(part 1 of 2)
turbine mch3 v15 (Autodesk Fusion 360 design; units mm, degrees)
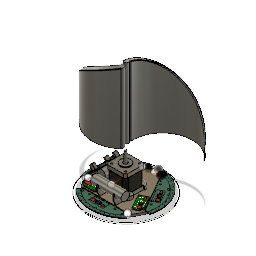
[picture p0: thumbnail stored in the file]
part number: 1uF
part number: ATTINY44-SSU
part number: 5v
part number: isp
part number: power
part number: 499
part number: rgb
parameter "Gapfit" = 0.1
parameter "GapSlide" = 0.3
parameter "RollDiameter" = 7
parameter "Screws" = 3
parameter "Bladediameter" = 250
parameter "Corediameter" = 25
parameter "Bladeball" = 10
sketch "Sketch1" plane through (0, 0, 0) normal (0, 1, 0) x axis (1, 0, 0)
  line L1 (-10, 0) -> (0, 0)
  circle C1 centre (0, 0) radius 125
  circle C2 centre (57.1021, -7.0184) radius 67.4682
  circle C3 centre (-22.4729, 52.9611) radius 67.4682
  circle C4 centre (-34.6292, -45.9427) radius 67.4682
  circle C5 centre (0, 0) radius 12.5
  circle C6 centre (-2.7386, 7.25) radius 5
  arc A1 centre (57.1187, -6.8729) radius 67.4697 clockwise from (-10, 0) to (124.0664, -15.249)
  arc A2 centre (61.6527, -10.7204) radius 62.5778 clockwise from (0, 0) to (124.0664, -15.249)
  arc A3 centre (2.8269, 10.2382) radius 1.879 clockwise from (2.1013, 8.505) to (3.3607, 12.0398)
  arc A4 centre (-21.5422, 58.753) radius 62.5778 clockwise from (0, 0) to (-48.8272, 115.0691)
  arc A5 centre (-22.6072, 52.9027) radius 67.4697 clockwise from (5, -8.6603) to (-48.8272, 115.0691)
  circle C7 centre (-4.9094, -5.9967) radius 5
  arc A6 centre (-10.28, -2.6709) radius 1.879 clockwise from (-8.4162, -2.4327) to (-12.1071, -3.1094)
  arc A7 centre (-40.1105, -48.0326) radius 62.5778 clockwise from (0, 0) to (-75.2392, -99.8202)
  arc A8 centre (-34.5115, -46.0298) radius 67.4697 clockwise from (5, 8.6603) to (-75.2392, -99.8202)
  circle C8 centre (7.648, -1.2533) radius 5
  arc A9 centre (7.4531, -7.5673) radius 1.879 clockwise from (6.3149, -6.0723) to (8.7464, -8.9303)
  point P6 (-10, 0)
  point P8 (0, 0)
  point P7 (0, 0)
  point P9 (-2.7386, 7.25)
  point P3 (57.1021, -7.0184)
  dimension "d1" diameter C1 = 250 (= "Bladediameter")
  dimension "d6" diameter C5 = 25
  dimension "d7" distance P6 P8 = 10
  dimension "d121" distance P7 P9 = 7.75
  dimension "d122" distance L1 P9 = 7.25
  dimension "d123" diameter C6 = 10 (= "Bladeball")
  dimension "d127" distance P3 P7 = 57.1021
  dimension "d133" radius A1 = 67.4697
  dimension "d134" radius A2 = 62.5778
  dimension "d135" radius A3 = 1.879
  dimension "d3" C-Pattern1-Angle = 360
  dimension "d137" C-Pattern2-Angle = 360
extrude "Extrude1" new body sketch "Sketch1" profile of C5 L1 C6 A1 A2 A3 A4 C7 A6 A7 C8 A9 along normal blind 150
extrude "Extrude2" new body sketch "Sketch1" profile of C5 C6 A1 A2 A3 A4 A5 C7 A6 A7 A8 C8 A9 along normal blind 150
extrude "Extrude1" new body sketch "Sketch1" profile of C5 L1 C6 along normal blind 120
combine "Combine1"
sketch "Sketch2"
  line L1 (0, 130) -> (0, 0)
  line L2 (-125, 0) -> (125, 0)
  line L3 (125, 150) -> (0, 150)
  line L4 (125, 0) -> (125, 150)
  line L5 (140, 150) -> (125, 150)
  line L6 (140, 0) -> (140, 150)
  line L7 (125, 0) -> (140, 0)
  line L8 (125, 150) -> (125, 0)
  arc A1 centre (-26.9994, 0.4171) radius 152 clockwise from (0, 150) to (125, 0)
  point P6 (0, 150)
  point P9 (0, 0)
  point P10 (125, 150)
  point P12 (140, 150)
  dimension "d18" angle L1 L2 = 90
  dimension "d114" distance P6 P9 = 150
  dimension "d115" radius A1 = 152
  dimension "d152" distance P10 P12 = 15
revolve "Revolve1" sketch "Sketch2" AlongAngle 360
sketch "Sketch3"
  line L1 (-160.3082, 0) -> (0, 0)
  line L2 (-12.5, 0) -> (12.5, 0)
  line L3 (-125, 0) -> (125, 0)
  line L4 (-9, -2) -> (0, -2)
  line L5 (0, 0) -> (0, -2)
  arc A1 centre (-9, -23.462) radius 21.462 clockwise from (-18.5775, -4.2555) to (-9, -2)
  arc A2 centre (54.8964, -102.7197) radius 122.8561 clockwise from (-18.5775, -4.2555) to (-12.5, 0)
  dimension "d23" distance L3 L4 = 2
revolve "Revolve2" sketch "Sketch3" AlongAngle 360
sketch "Sketch4" plane through (0, -2, 0) normal (0, -1, 0) x axis (1, 0, 0)
  circle C1 centre (0, 0) radius 9
sketch "Sketch1" plane through (0, 0, 0) normal (0, 1, 0) x axis (1, 0, 0)
  line L1 (-20.95, -20.95) -> (20.95, -20.95)
  line L2 (-20.95, 20.95) -> (-20.95, -20.95)
  line L3 (20.95, 20.95) -> (-20.95, 20.95)
  line L4 (20.95, -20.95) -> (20.95, 20.95)
  line L5 (-20.95, 20.95) -> (20.95, -20.95)
  line L6 (20.95, 20.95) -> (-20.95, -20.95)
  line L7 (20.95, 16.85) -> (16.85, 20.95)
  line L8 (-16.85, -20.95) -> (-20.95, -16.85)
  line L9 (0, -20.95) -> (0, 20.95)
  line L10 (16.85, -20.95) -> (20.95, -16.85)
  line L11 (-20.95, 16.85) -> (-16.85, 20.95)
  line L12 (-1.9, -1.6248) -> (-1.9, 1.6248)
  circle C1 centre (14.8, 14.8) radius 2.05
  circle C2 centre (0, 0) radius 11
  circle C3 centre (-14.8, 14.8) radius 2.05
  circle C4 centre (-14.8, -14.8) radius 2.05
  circle C5 centre (14.8, -14.8) radius 2.05
  circle C6 centre (0, 0) radius 4.5
  circle C7 centre (0, 0) radius 2.5
  point P2 (20.95, -20.95)
  point P3 (-20.95, -20.95)
  point P5 (20.95, 20.95)
  point P7 (14.8, 14.8)
  point P13 (20.95, 16.85)
  point P22 (0, 0)
  dimension "d1_1" distance P2 P3 = 41.9
  dimension "d2_1" distance P2 P5 = 41.9
  dimension "d3_1" diameter C1 = 4.1
  dimension "d4" distance L4 P7 = 6.15
  dimension "d5" diameter C2 = 22
  dimension "d8_1" distance L3 P13 = 4.1
  dimension "d9_1" diameter C6 = 9
  dimension "d10" diameter C7 = 5
  dimension "d11" distance P22 L12 = 1.9
  dimension "d7_1" C-Pattern1-Angle = 360
extrude "Extrude1" new body sketch "Sketch1" profile of L1 L2 L3 L4 C1 C2 C3 C4 C5 L7 L8 L10 L11 along normal blind 8 named "d12_1"
extrude "Extrude2" add sketch "Sketch1" profile of C2 C6 along normal blind 10 named "d14_1"
extrude "Extrude3" new body sketch "Sketch1" profile of C7 L12 along normal blind 22.3 named "d16_1"
extrude "Extrude4" add sketch "Sketch1" profile of C7 L12 along normal blind 11 named "d18_1"
extrude "Extrude5" add sketch "Sketch1" profile of C6 C7 along normal blind 7 named "d20_1"
extrude "Extrude6" add of existing geometry blind 10
sketch "Sketch2" plane through (0, 0, 0) normal (0, 1, 0) x axis (1, 0, 0)
  line L1 (-20.95, -20.95) -> (20.95, -20.95)
  line L2 (20.95, -20.95) -> (20.95, 20.95)
  line L3 (20.95, 16.85) -> (20.95, -16.85)
  line L4 (20.95, -16.85) -> (20.95, 16.85)
  line L5 (20.95, -14.0216) -> (14.0216, -20.95)
  line L6 (16.85, -20.95) -> (20.95, -16.85)
  line L7 (20.95, 20.95) -> (-20.95, -20.95)
  line L8 (0, -20.95) -> (0, 20.95)
  line L9 (0, 19) -> (0, -20.95)
  line L10 (-14.0216, 20.95) -> (-20.95, 14.0216)
  line L11 (14.0216, 20.95) -> (20.95, 14.0216)
  line L12 (-20.95, -14.0216) -> (-14.0216, -20.95)
  line L13 (-20.95, -14.0216) -> (-20.95, 14.0216)
  line L14 (14.0216, -20.95) -> (-14.0216, -20.95)
  line L15 (20.95, 14.0216) -> (20.95, -14.0216)
  line L16 (-14.0216, 20.95) -> (14.0216, 20.95)
  dimension "d24_1" angle L1 L5 = 45
  dimension "d25_1" distance L5 L6 = 2
extrude "Extrude7" add sketch "Sketch2" profile of L1 L2 L3 L4 L5 L8 L10 L11 L12 L13 L14 L15 L16 against normal blind 30
work_plane "WorkPlane1" sketch "Sketch1" AlongDistance -15
split "Split1"
sketch "Sketch3" plane through (0, -15, 0) normal (0, 1, 0) x axis (1, 0, 0)
  line L1 (0, 35) -> (0, -30)
copy_paste_bodies "CopyPasteBodies1"
move "Move1" RotateAngle 180
work_plane "WorkPlane2" AlongDistance 0
combine "Combine1"
combine "Combine2"
combine "Combine3"
combine "Combine4"
sketch "Sketch4" plane through (0, -38, 0) normal (0, -1, 0) x axis (1, 0, 0)
  circle C1 centre (0, 0) radius 19.3452
extrude "Extrude8" cut sketch "Sketch4" along normal blind 30
sketch "Sketch5" plane through (0, 0, -20.95) normal (0, 0, -1) x axis (-1, 0, 0)
  line L1 (-16.85, -30) -> (-14.0216, -30)
  line L2 (-16.85, -38) -> (-16.85, -30)
  line L3 (16.85, -38) -> (-16.85, -38)
  line L4 (16.85, -30) -> (16.85, -38)
  line L5 (14.0216, -30) -> (16.85, -30)
  line L6 (14.0216, 0) -> (14.0216, -30)
  line L7 (16.85, 0) -> (14.0216, 0)
  line L8 (16.85, 8) -> (16.85, 0)
  line L9 (-16.85, 8) -> (16.85, 8)
  line L10 (-16.85, 0) -> (-16.85, 8)
  line L11 (-14.0216, 0) -> (-16.85, 0)
  line L12 (-14.0216, -30) -> (-14.0216, 0)
  line L13 (3.75, -30) -> (-3.75, -30)
  line L14 (3.75, -37.5) -> (3.75, -30)
  line L15 (-3.75, -37.5) -> (3.75, -37.5)
  line L16 (-3.75, -30) -> (-3.75, -37.5)
  line L17 (14.0216, -30) -> (-14.0216, -30)
  line L18 (0, -30) -> (0, -37.5)
  point P14 (-3.75, -30)
  point P15 (3.75, -30)
  point P16 (3.75, -37.5)
  dimension "d33" distance P14 P15 = 7.5
  dimension "d34" distance P15 P16 = 7.5
  dimension "d35" distance L3 L15 = 0.5
  dimension "d38" distance L4 L14 = 13.1
  dimension "d39" = 13.2
extrude "Extrude9" cut sketch "Sketch5" profile of L13 L14 L15 L16 against normal blind 1
sketch "Sketch5" plane through (0, -42, 0) normal (0, 1, 0) x axis (-1, 0, 0)
  line L1 (16.85, -20.95) -> (-16.85, -20.95)
  line L2 (20.95, -16.85) -> (16.85, -20.95)
  line L3 (20.95, 16.85) -> (20.95, -16.85)
  line L4 (16.85, 20.95) -> (20.95, 16.85)
  line L5 (-16.85, 20.95) -> (16.85, 20.95)
  line L6 (-20.95, 16.85) -> (-16.85, 20.95)
  line L7 (-20.95, -16.85) -> (-20.95, 16.85)
  line L8 (-16.85, -20.95) -> (-20.95, -16.85)
  line L9 (-14.0216, -20.95) -> (-20.95, -14.0216)
  line L10 (-17.4858, -17.4858) -> (0, 0)
  circle C1 centre (14.8, 14.8) radius 2.05
  circle C2 centre (14.8, -14.8) radius 2.05
  circle C3 centre (-14.8, 14.8) radius 2.05
  circle C4 centre (0, 0) radius 11
  circle C5 centre (-14.8, -14.8) radius 2.05
work_plane "WorkPlane1" RotateAngle 0
sketch "Sketch6" plane through (0, -50, 0) normal (0.7071, 0, 0.7071) x axis (0.7071, 0, -0.7071)
  line L1 (24.7286, 8) -> (0, 8)
  line L2 (24.7286, 18) -> (24.7286, 8)
  line L3 (2.8991, 8) -> (26.7286, 8)
  line L4 (14.8139, 8) -> (24.7286, 8)
  line L5 (14.8139, 10) -> (14.8139, 8)
  line L6 (14.8139, 11) -> (14.8139, 10)
work_plane "WorkPlane2" sketch "Sketch1" AlongDistance 0
split "Split4" bodies "top"
work_plane "WorkPlane3" AlongDistance -30
split "Split5" bodies "middle"
sketch "Top view" plane through (0, 0, 0) normal (0, 1, 0) x axis (1, 0, 0)
  curve K1 (19.1192, 0) -> (9.0783, 0)
  curve K2 (14.0987, 3.55) -> (14.0987, -3.55)
  line L1 (12.7925, 3.4277) -> (0, 0)
  line L2 (12.311, 4.6914) -> (0, 0)
  line L3 (12.311, 4.6914) -> (12.7925, 3.4277)
  circle C1 centre (0, 0) radius 14.0987
  closed curve K3 centre (14.0987, 0)
  circle C2 centre (14.0987, 0) radius 5.0205
  dimension "d10_1" = 7.1 (= "RollDiameter + Gapfit")
  dimension "d11_1" distance K3 = 10.0409 (= "sqrt(2) * d10_1")
  dimension "d12_2" angle K1 L1 = 15 (= "( 180 / NumRolls ) * 1 deg")
sketch "Bearing view"
  line L1 (19.1192, 0) -> (9.0783, 0)
  line L2 (9.0783, 0) -> (19.1192, 0)
  line L3 (14.0987, -5.0205) -> (9.0783, 0)
  line L4 (19.1192, 0) -> (14.0987, -5.0205)
  line L5 (14.0987, 5.0205) -> (9.0783, 0)
  line L6 (19.1192, 0) -> (14.0987, 5.0205)
  line L7 (16.6089, -2.5102) -> (11.5885, 2.5102)
  line L8 (16.6089, 2.5102) -> (11.5885, -2.5102)
  line L9 (14.0987, 5.0205) -> (14.0987, -5.0205)
  line L10 (18.5181, 0.1768) -> (17.3868, 1.3081)
  line L11 (18.2593, -0.7891) -> (18.5181, 0.1768)
  line L12 (14.8879, -4.1606) -> (18.2593, -0.7891)
  line L13 (13.9219, -4.4194) -> (14.8879, -4.1606)
  line L14 (12.7906, -3.288) -> (13.9219, -4.4194)
  line L15 (17.3868, 1.3081) -> (12.7906, -3.288)
  line L16 (24.1757, 0) -> (18.7757, 0)
  line L17 (24.1757, -5.0205) -> (24.1757, 0)
  line L18 (14.8987, -5.0205) -> (24.1757, -5.0205)
  line L19 (14.8987, -4.2912) -> (14.8987, -5.0205)
  line L20 (18.4828, -0.7071) -> (14.8987, -4.2912)
  line L21 (24.1757, 5.0205) -> (24.1757, 0)
  line L22 (14.8987, 5.0205) -> (24.1757, 5.0205)
  line L23 (14.8987, 4.2912) -> (14.8987, 5.0205)
  line L24 (18.4828, 0.7071) -> (14.8987, 4.2912)
  line L25 (4.0218, -5.0205) -> (4.0218, 0)
  line L26 (4.0218, 5.0205) -> (4.0218, 0)
  line L27 (9.7147, 0.7071) -> (13.2987, 4.2912)
  line L28 (9.7147, -0.7071) -> (13.2987, -4.2912)
  line L29 (13.2987, -4.2912) -> (13.2987, -5.0205)
  line L30 (13.2987, -5.0205) -> (4.0218, -5.0205)
  line L31 (13.2987, 5.0205) -> (4.0218, 5.0205)
  line L32 (13.2987, 4.2912) -> (13.2987, 5.0205)
  line L33 (9.4218, 0) -> (4.0218, 0)
  line L34 (19.5757, -5.0205) -> (19.5757, 5.0205)
  line L35 (21.0757, 5.0205) -> (21.0757, -5.0205)
  line L36 (22.5757, -5.0205) -> (22.5757, 5.0205)
  line L37 (7.1218, 5.0205) -> (7.1218, -5.0205)
  line L38 (5.6218, -5.0205) -> (5.6218, 5.0205)
  line L39 (4.0218, 5.0205) -> (0, 5.0205)
  line L40 (4.0218, -5.0205) -> (4.0218, 5.0205)
  line L41 (0, -5.0205) -> (4.0218, -5.0205)
  line L42 (0, 5.0205) -> (0, -5.0205)
  line L43 (0, 0) -> (4.0218, 0)
  arc A1 centre (17.7757, 0) radius 1 clockwise from (18.7757, 0) to (18.4828, -0.7071)
  arc A2 centre (17.7757, 0) radius 1 clockwise from (18.4828, 0.7071) to (18.7757, 0)
  arc A3 centre (10.4218, 0) radius 1 clockwise from (9.4218, 0) to (9.7147, 0.7071)
  arc A4 centre (10.4218, 0) radius 1 clockwise from (9.7147, -0.7071) to (9.4218, 0)
  point P16 (13.9219, -4.4194)
  point P17 (12.7906, -3.288)
  point P6 (14.0987, -5.0205)
  point P31 (18.7757, 0)
  dimension "d32_1" distance L4 L12 = 0.05 (= "Gapfit / 2")
  dimension "d33_1" distance L3 L14 = 0.3 (= "GapSlide")
  dimension "d34_1" angle L13 L14 = 60
  dimension "d35_1" distance L12 P16 = 0.5
  dimension "d36_1" distance P16 P17 = 1.6
  dimension "d45" distance L4 L20 = 0.05 (= "Gapfit / 2")
  dimension "d46" distance P6 L19 = 0.8
  dimension "d47" radius A1 = 1
  dimension "d53" distance P31 L34 = 0.8
  dimension "d54" distance L34 L36 = 3 (= "Screws")
  dimension "d55" distance L21 L36 = 1.6
revolve "Revolve1" sketch "Bearing view" AlongAngle 360 named "d37_1"
circular_pattern "C-Pattern1" countU 6 (= "NumRolls / 2") named "d38_1" TotalAngle 360 named "d39_1"
revolve "Revolve1" sketch "Bearing view" AlongAngle 360 named "d40_1"
move "Move1" RotateAngle 180 named "d41_1"
move "Move2" RotateAngle 30 (= "( 360 / NumRolls ) * 1 deg")
circular_pattern "C-Pattern1" countU 6 (= "NumRolls / 2") TotalAngle 360
revolve "Revolve1" sketch "Bearing view" AlongAngle 360 bodies "Race outer"
revolve "Revolve1" sketch "Bearing view" AlongAngle 360
copy_paste_bodies "CutPasteBodies1"
revolve "Revolve1" sketch "Bearing view" AlongAngle 360 bodies "Race inner top"
revolve "Revolve2" sketch "Bearing view" AlongAngle 360
circular_pattern "C-Pattern1" TotalAngle 360
revolve "Revolve2" sketch "Bearing view" AlongAngle 360
circular_pattern "C-Pattern1" TotalAngle 360
fillet "Fillet1" radius 0.4
fillet "Fillet2" radius 0.4
position "Position1"
extrude "Extrude1" add of existing geometry blind 2.98
revolve "Revolve3" sketch "Bearing view" AlongAngle 360
revolve "Revolve4" sketch "Bearing view" AlongAngle 360 bodies "Race inner top"
combine "Combine1"
work_plane "WorkPlane4" AlongDistance 8
split "Split1" bodies "Race inner top"
position "Position2"
sketch "Sketch7" plane through (0, -2, 0) normal (0, -1, 0) x axis (1, 0, 0)
  circle C1 centre (0, 0) radius 9
position "Position3"
position "Position4"
extrude "Extrude3" add of existing geometry blind 10
sketch "Sketch8"
  line L1 (9, -27) -> (-9, -27)
  line L2 (1.593, 101.3922) -> (1.593, -15)
  line L3 (11, -27) -> (0, -27)
  line L4 (13, -27) -> (13, -29)
  line L5 (11, -27) -> (13, -27)
  line L6 (-15.2987, -28.9795) -> (15.2987, -28.9795)
  line L7 (9, -28.9795) -> (9, -27)
  line L8 (-18.5775, -19.2555) -> (18.5775, -19.2555)
  line L9 (13, -19.2555) -> (13, -29)
  line L10 (9, -19.2555) -> (13, -19.2555)
  line L11 (11, -23) -> (9, -23)
  line L12 (11, -27) -> (11, -23)
  line L13 (11, -27) -> (9, -27)
  line L14 (9, -19.2555) -> (9, -23)
  line L15 (10.8, -23.2) -> (9, -23.2)
  line L16 (10.8, -27) -> (10.8, -23.2)
  line L17 (10.8, -27) -> (9, -27)
  line L18 (9, -27) -> (9, -23.2)
  line L19 (11, -19.2555) -> (11, -23)
  line L20 (9, -27) -> (9, -23)
  line L21 (15.2987, -19.0267) -> (15.2987, -28.9795)
  line L22 (12.5, -15) -> (18.5775, -19.2555)
  line L23 (20.95, -88) -> (20.95, -92)
  line L24 (-16.85, -88) -> (16.85, -88)
  line L25 (0, -88) -> (0, -92)
  line L26 (76.6506, -92) -> (0, -92)
  line L27 (0, -88) -> (75.5922, -88)
  line L28 (24.1757, -29.3795) -> (24.1757, -38.6205)
  line L29 (23.7757, -28.9795) -> (15.2987, -28.9795)
  line L30 (23.7757, -28.9795) -> (24.1757, -29.3795)
  line L31 (78.096, -100.3794) -> (80.0853, -100.3794)
  line L32 (24.1757, -29.3795) -> (24.1757, -38.6205)
  line L33 (24.1757, -29.3795) -> (23.7757, -28.9795)
  arc A1 centre (-5.4766, -109.9537) radius 86.0959 clockwise from (23.7757, -28.9795) to (80.0853, -100.3794)
  arc A2 centre (6.5799, -108.4006) radius 71.9645 clockwise from (24.1757, -38.6205) to (78.096, -100.3794)
  point P30 (20.95, -88)
  point P31 (20.95, -92)
  dimension "d75" distance L11 L15 = 0.2
  dimension "d76" distance L12 L16 = 0.2
  dimension "d96" distance P30 P31 = 4
revolve "Revolve3" sketch "Sketch8" AlongAngle 360
combine "Combine3"
extrude "Extrude4" add of existing geometry blind 2
revolve "Revolve1" sketch "Sketch8" AlongAngle -30
circular_pattern "C-Pattern1" TotalAngle 360
combine "Combine4"
revolve "Revolve8" sketch "Sketch8" AlongAngle 360
revolve "Revolve2" sketch "Sketch8" AlongAngle 30 bodies "race inner"
revolve "Revolve4" sketch "Sketch8" AlongAngle 60
circular_pattern "C-Pattern3" TotalAngle 360
combine "Combine1"
work_plane "WorkPlane5" AlongDistance 0
work_plane "WorkPlane6" AlongDistance 4
sketch "Sketch11" plane through (0, -88, 0) normal (0, -1, 0) x axis (1, 0, 0)
  line L1 (16.85, -20.95) -> (-16.85, -20.95)
  line L2 (20.95, -16.85) -> (16.85, -20.95)
  line L3 (20.95, 16.85) -> (20.95, -16.85)
  line L4 (16.85, 20.95) -> (20.95, 16.85)
  line L5 (-16.85, 20.95) -> (16.85, 20.95)
  line L6 (-20.95, 16.85) -> (-16.85, 20.95)
  line L7 (-20.95, -16.85) -> (-20.95, 16.85)
  line L8 (-16.85, -20.95) -> (-20.95, -16.85)
  circle C1 centre (0, 0) radius 4.5
  circle C2 centre (14.8, 14.8) radius 2.05
  circle C3 centre (-14.8, 14.8) radius 2.05
  circle C4 centre (14.8, -14.8) radius 2.05
  circle C5 centre (-14.8, -14.8) radius 2.05
  circle C6 centre (-14.8, 14.8) radius 2.05
  circle C7 centre (14.8, 14.8) radius 2.05
  circle C8 centre (14.8, -14.8) radius 2.05
  circle C9 centre (-14.8, -14.8) radius 2.05
sketch "Sketch12" plane through (0, -34, 0) normal (0, -1, 0) x axis (1, 0, 0)
  line L1 (-1.9, 1.6248) -> (-1.9, -1.6248)
  circle C1 centre (0, 0) radius 9.4218
  circle C2 centre (5.0358, 5.0358) radius 1.5
  circle C3 centre (0, 7.1218) radius 1.5
  circle C4 centre (-5.0358, 5.0358) radius 1.5
  circle C5 centre (-7.1218, 0) radius 1.5
  circle C6 centre (-5.0358, -5.0358) radius 1.5
  circle C7 centre (0, -7.1218) radius 1.5
  circle C8 centre (7.1218, 0) radius 1.5
  circle C9 centre (5.0358, -5.0358) radius 1.5
  arc A1 centre (0, 0) radius 2.5 clockwise from (-1.9, 1.6248) to (-1.9, -1.6248)
  circle C10 centre (0, 0) radius 2.5
copy_paste_bodies "CutPasteBodies3"
position "Position7"
combine "Combine2"
combine "Combine3"
combine "Combine1"
revolve "Revolve6" sketch "Sketch2" AlongAngle 180
revolve "Revolve7" sketch "Sketch2" AlongAngle -180
split "Split1"
combine "Combine2"
sketch "Sketch15" plane through (0, -14, 0) normal (0, -1, 0) x axis (1, 0, 0)
  line L1 (-1.9, 1.6248) -> (-1.9, -1.6248)
  arc A1 centre (0, 0) radius 2.5 clockwise from (-1.9, 1.6248) to (-1.9, -1.6248)
  circle C1 centre (0, 0) radius 9
extrude "Extrude2" cut sketch "Sketch12" profile of L1 C10 against normal blind 31
extrude "Extrude3" cut of existing geometry to an object
revolve "Revolve8" sketch "Sketch2" AlongAngle 360
revolve "Revolve6" sketch "Sketch8" AlongAngle 360
revolve "Revolve7" sketch "Sketch8" AlongAngle 360
ground "Ground1"
sketch "Sketch16" plane through (0, 0, 0) normal (0, 1, 0) x axis (1, 0, 0)
as_built_joint "As-built2"
position "Position8"
sketch "Sketch17"
  line L1 (18.5775, -19.2555) -> (43, -37)
  line L2 (138.1715, -105.0631) -> (15.2987, -19.0267)
  line L3 (40.6813, -36.7998) -> (15.2987, -19.0267)
  line L4 (43, -37) -> (40.6813, -36.7998)
  line L5 (12.5, -15) -> (18.5775, -19.2555)
  line L6 (15.5388, -17.1278) -> (15.2987, -19.0267)
  line L7 (15.5388, -17.1278) -> (18.5775, -19.2555)
revolve "Revolve3" sketch "Sketch17" AlongAngle 360
move "Move1"
move "Move2" RotateAngle 25
fillet "Fillet1" radius 1
fillet "Fillet2" radius 1
revolve "Revolve8" sketch "Sketch8" AlongAngle 360
revolve "Revolve9" sketch "Sketch8" AlongAngle 360
component_from_bodies "Body->Comp"
sketch "Sketch18" plane through (0, -88, 0) normal (0, 1, 0) x axis (-1, 0, 0)
  circle C1 centre (0, 0) radius 75.5922
pcb "PCB" BoardHeight 1.57 named "d1_2"
position "Position9"
sketch "Sketch19" plane through (0, -90, 0) normal (0, -1, 0) x axis (1, 0, 0)
  line L1 (-52.744, 40.167) -> (-52.641, 74.634)
  line L2 (52.118, 39.984) -> (-52.744, 40.167)
  line L3 (51.967, 74.579) -> (52.118, 39.984)
  line L4 (-52.641, 74.634) -> (51.967, 74.579)
  circle C1 centre (-11.43, 47.272) radius 0.175
  circle C2 centre (-5.461, 64.925) radius 0.175
  circle C3 centre (-26.924, 63.655) radius 0.175
  circle C4 centre (-34.544, 60.861) radius 0.175
  circle C5 centre (14.478, 63.401) radius 0.175
  circle C6 centre (21.336, 61.369) radius 0.175
  circle C7 centre (-44.584, 53.756) radius 0.175
  circle C8 centre (27.273, 58.035) radius 0.175
  circle C9 centre (-11.303, 49.558) radius 0.175
  circle C10 centre (-17.907, 62.766) radius 0.175
  circle C11 centre (18.796, 59.21) radius 0.175
  circle C12 centre (41.275, 51.59) radius 0.175
  circle C13 centre (48.514, 48.161) radius 0.175
  circle C14 centre (7.239, 68.608) radius 0.175
  circle C15 centre (22.225, 64.925) radius 0.175
  circle C16 centre (36.068, 58.194) radius 0.175
  circle C17 centre (44.704, 44.478) radius 0.175
  circle C18 centre (-2.54, 47.907) radius 0.175
  circle C19 centre (39.243, 55.908) radius 0.175
  circle C20 centre (28.956, 62.385) radius 0.175
  circle C21 centre (15.24, 66.957) radius 0.175
  circle C22 centre (-9.525, 65.179) radius 0.175
  circle C23 centre (42.672, 53.368) radius 0.175
  circle C24 centre (34.163, 54.765) radius 0.175
  circle C25 centre (-5.461, 62.766) radius 0.175
  circle C26 centre (42.672, 48.161) radius 0.175
  circle C27 centre (36.83, 52.987) radius 0.175
  circle C28 centre (-38.1, 58.575) radius 0.175
  circle C29 centre (-25.908, 61.369) radius 0.175
  circle C30 centre (-5.461, 69.243) radius 0.175
  circle C31 centre (1.905, 68.989) radius 0.175
  circle C32 centre (-42.862, 51.272) radius 0.175
  circle C33 centre (4.956, 63.524) radius 0.175
  circle C34 centre (-44.704, 46.383) radius 0.175
  circle C35 centre (-15.494, 47.272) radius 0.175
  circle C36 centre (-36, 58) radius 3.0397
  circle C37 centre (-28.8597, 61.8637) radius 3.0397
  circle C38 centre (-21.3112, 64.8524) radius 3.0397
  circle C39 centre (-13.4613, 66.9238) radius 3.0397
  circle C40 centre (-5.4209, 68.0486) radius 3.0397
  circle C41 centre (2.6961, 68.2109) radius 3.0397
  circle C42 centre (10.7749, 67.4085) radius 3.0397
  circle C43 centre (18.7014, 65.6526) radius 3.0397
  circle C44 centre (26.3634, 62.968) radius 3.0397
  circle C45 centre (33.6524, 59.3929) radius 3.0397
  circle C46 centre (40.4655, 54.9777) radius 3.0397
  circle C47 centre (46.7062, 49.7848) radius 3.0397
  dimension "d170" C-Pattern1-Angle = -75
remove_instance "RemoveInstance1"
pcb "PCB" BoardHeight 1.57 named "d1_3"
position "Position11"
work_plane "WorkPlane8" AlongDistance 0
sketch "Sketch20" plane through (0, -88, 0) normal (0, -1, 0) x axis (1, 0, 0)
  line L1 (46.092, 43.282) -> (54.22, 52.172)
  line L2 (54.22, 52.172) -> (46.092, 43.282)
  line L3 (20, 46) -> (-26, 46)
  line L4 (20, 58) -> (20, 46)
  line L5 (-26, 58) -> (20, 58)
  line L6 (-26, 46) -> (-26, 58)
  line L7 (-46.11, 43.282) -> (-55, 52.172)
  line L8 (-46.4835, 42.382) -> (-49.2565, 45.1551)
  line L9 (-46.11, 43.282) -> (46.092, 43.282)
  line L10 (46.4886, 42.382) -> (-46.4835, 42.382)
  line L11 (49.14, 45.2819) -> (46.4886, 42.382)
  line L12 (-63.7853, 19.9155) -> (-59.9482, 19.0693)
  line L13 (-59.9482, 19.0693) -> (-13.4622, -61.4469)
  line L14 (-13.4622, -61.4469) -> (-14.4772, -65.235)
  line L15 (-26.8372, -45.5167) -> (-37.2295, -51.5167)
  line L16 (-49.8372, -5.6795) -> (-26.8372, -45.5167)
  line L17 (-37.2295, -51.5167) -> (-60.2295, -11.6795)
  line L18 (-60.2295, -11.6795) -> (-49.8372, -5.6795)
  line L19 (14.6453, -65.1974) -> (13.4596, -61.4513)
  line L20 (13.4596, -61.4513) -> (59.9456, 19.0649)
  line L21 (59.9456, 19.0649) -> (63.7337, 20.0799)
  line L22 (52.8372, -0.4833) -> (63.2295, -6.4833)
  line L23 (29.8372, -40.3205) -> (52.8372, -0.4833)
  line L24 (63.2295, -6.4833) -> (40.2295, -46.3205)
  line L25 (40.2295, -46.3205) -> (29.8372, -40.3205)
  circle C1 centre (0, 0) radius 74.8422
  arc A1 centre (-1.9164, 1.5567) radius 77.2302 clockwise from (72.6823, 21.5454) to (18.0723, -73.0419)
  circle C2 centre (0, 0) radius 66.8221
  arc A2 centre (2.8846, 66.1916) radius 1.7023 clockwise from (4.5184, 66.6691) to (1.2984, 66.8095)
  arc A3 centre (-58.7659, -30.5977) radius 1.7023 clockwise from (-59.9964, -29.4215) to (-58.5079, -32.2803)
  arc A4 centre (55.8813, -35.5939) radius 1.7023 clockwise from (55.4779, -37.2477) to (57.2095, -34.5292)
  dimension "d231" distance L7 L8 = 0.9005
  dimension "d232" distance L9 L10 = 0.9
  dimension "d233" distance L2 L11 = 0.9
sketch "Sketch21" plane through (0, -89, 0) normal (0, 1, 0) x axis (-1, 0, 0)
  line L1 (-60.5383, 18.2914) -> (-63.9987, 19.2186)
  line L2 (-14.4373, -61.5578) -> (-60.5383, 18.2914)
  line L3 (-15.5248, -64.9936) -> (-14.4373, -61.5578)
  line L4 (14.4283, -61.5734) -> (15.3555, -65.0338)
  line L5 (60.5293, 18.2758) -> (14.4283, -61.5734)
  line L6 (64.0485, 19.0519) -> (60.5293, 18.2758)
  line L7 (46.11, 43.282) -> (48.6432, 45.8152)
  line L8 (-46.092, 43.282) -> (46.11, 43.282)
  line L9 (-48.5237, 45.9417) -> (-46.092, 43.282)
  line L10 (-16.85, 20.95) -> (16.85, 20.95)
  line L11 (16.85, 20.95) -> (-16.85, 20.95)
  line L12 (16.85, 20.95) -> (-16.85, 20.95)
  line L13 (-14.0216, 20.95) -> (14.0216, 20.95)
  line L14 (-4.7919, 20.95) -> (4.7919, 20.95)
  line L15 (0, -35) -> (0, 30)
  line L16 (-4.7919, 30) -> (4.7919, 30)
  line L17 (-4.7919, 20.95) -> (-4.7919, 30)
  line L18 (4.7919, 20.95) -> (4.7919, 30)
  line L19 (-4.7919, 20.95) -> (4.7919, 20.95)
  arc A1 centre (0, 0) radius 66.8221 clockwise from (15.3555, -65.0338) to (-15.5248, -64.9936)
  arc A2 centre (0, 0) radius 66.8221 clockwise from (48.6432, 45.8152) to (64.0485, 19.0519)
  arc A3 centre (0, 0) radius 66.8221 clockwise from (-63.9987, 19.2186) to (-48.5237, 45.9417)
sketch "Sketch22" plane through (17.4858, 0, 17.4858) normal (0.7071, 0, 0.7071) x axis (0.7071, 0, -0.7071)
  line L1 (-4.8991, -80) -> (-4.8991, -50)
  line L2 (4.8991, -80) -> (-4.8991, -80)
  line L3 (4.8991, -50) -> (4.8991, -80)
  line L4 (-4.8991, -50) -> (4.8991, -50)
  line L5 (-2.8991, -80) -> (-26.7286, -80)
  line L6 (4.8991, -80) -> (-6.9957, -80)
  line L7 (26.7286, -88) -> (2.8991, -88)
  line L8 (4.8991, -88) -> (4.8991, -80)
  line L9 (33.3366, -89) -> (-55.7237, -89)
  line L10 (4.8991, -89) -> (4.8991, -88)
  line L11 (6.7296, -78.9998) -> (6.7296, -89)
  line L12 (4.8991, -77.8864) -> (6.7296, -78.9998)
  line L13 (-4.8991, -77.8182) -> (4.8991, -77.8864)
  line L14 (-4.8991, -77.8182) -> (-6.9957, -80)
  line L15 (-2.8991, -80) -> (-6.9957, -80)
  line L16 (4.8991, -80) -> (-6.9957, -80)
  line L17 (12.0731, -80.9886) -> (6.7296, -80.9886)
  arc A1 centre (2.303, -85.0395) radius 10.5766 clockwise from (-6.9957, -80) to (12.4568, -88)
extrude "Extrude1" new body sketch "Sketch22" profile of L1 L2 L3 L5 L6 L7 L8 L9 L10 L11 L12 L13 L14 L15 L16 A1 along normal blind 3
revolve "Revolve1" AlongAngle 90
extrude "Extrude1" new body blind 2
extrude "Extrude2" cut of existing geometry blind 10
remove_instance "RemoveInstance2"
remove_instance "RemoveInstance3"
pcb "PCB" BoardHeight 1.57 named "d1_5"
remove_instance "RemoveInstance4"
position "Position13"
step "C-Pattern" TotalAngle 360
extrude "Extrude1" new body sketch "Sketch20" along normal blind 5
extrude "Extrude2" cut sketch "Sketch20" profile of C1 A1 C2 L1 L2 L7 along normal blind 5
extrude "Extrude3" cut sketch "Sketch20" profile of L3 L4 L5 L6 L15 L16 L17 L18 L22 L23 L24 L25 along normal blind 2
extrude "Extrude4" cut sketch "Sketch20" profile of C2 L1 L2 L3 L4 L5 L6 A2 L7 L9 L12 L13 L14 L15 L16 L17 L18 A3 L19 L20 L21 L22 L23 L24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 along normal blind 0.5
sketch "Sketch24" plane through (0, -88, 0) normal (0, -1, 0) x axis (1, 0, 0)
  line L1 (16.85, -20.95) -> (-16.85, -20.95)
  line L2 (20.95, -16.85) -> (16.85, -20.95)
  line L3 (20.95, 16.85) -> (20.95, -16.85)
  line L4 (16.85, 20.95) -> (20.95, 16.85)
  line L5 (-16.85, 20.95) -> (16.85, 20.95)
  line L6 (-20.95, 16.85) -> (-16.85, 20.95)
  line L7 (-20.95, -16.85) -> (-20.95, 16.85)
  line L8 (-16.85, -20.95) -> (-20.95, -16.85)
  line L9 (11, 45) -> (-20, 45)
  line L10 (11, 59) -> (11, 45)
  line L11 (-20, 59) -> (11, 59)
  line L12 (-20, 45) -> (-20, 59)
  line L13 (-41.0955, -46.8205) -> (-56.5955, -19.9737)
  line L14 (-44.4711, -12.9737) -> (-28.9711, -39.8205)
  line L15 (-56.5955, -19.9737) -> (-44.4711, -12.9737)
  line L16 (-28.9711, -39.8205) -> (-41.0955, -46.8205)
  line L17 (61.0955, -12.1795) -> (45.5955, -39.0263)
  line L18 (33.4711, -32.0263) -> (48.9711, -5.1795)
  line L19 (45.5955, -39.0263) -> (33.4711, -32.0263)
  line L20 (48.9711, -5.1795) -> (61.0955, -12.1795)
  line L21 (26.2941, 8.6775) -> (22.2443, 12.7273)
  circle C1 centre (0, 0) radius 4.5
  circle C2 centre (14.8, 14.8) radius 2.05
  circle C3 centre (-14.8, 14.8) radius 2.05
  circle C4 centre (14.8, -14.8) radius 2.05
  circle C5 centre (-14.8, -14.8) radius 2.05
  circle C6 centre (-28.584, 47.314) radius 1.778
  circle C7 centre (-28.584, 47.314) radius 1.778
  circle C8 centre (-28.584, 47.314) radius 1
  circle C9 centre (25.518, 47.314) radius 1.778
  circle C10 centre (25.518, 47.314) radius 1.778
  circle C11 centre (25.518, 47.314) radius 1
  circle C12 centre (-26.6831, -48.4115) radius 1.778
  circle C13 centre (-53.7341, -1.5578) radius 1
  circle C14 centre (-26.6831, -48.4115) radius 1
  circle C15 centre (-53.7341, -1.5578) radius 1.778
  circle C16 centre (-26.6831, -48.4115) radius 1.778
  circle C17 centre (-53.7341, -1.5578) radius 1.778
  circle C18 centre (55.2671, 1.0975) radius 1.778
  circle C19 centre (28.2161, -45.7562) radius 1
  circle C20 centre (55.2671, 1.0975) radius 1
  circle C21 centre (28.2161, -45.7562) radius 1.778
  circle C22 centre (55.2671, 1.0975) radius 1.778
  circle C23 centre (28.2161, -45.7562) radius 1.778
  arc A1 centre (16.4647, 12.6032) radius 10.5843 clockwise from (12.5391, 22.4325) to (26.2941, 8.6775)
  arc A2 centre (13.8805, 14.0687) radius 8.4707 clockwise from (12.5391, 22.4325) to (22.2443, 12.7273)
  dimension "d244" diameter C8 = 2
  dimension "d245" diameter C11 = 2
  dimension "d257" C-Pattern1-Angle = 360
extrude "Extrude5" cut of existing geometry blind -2
extrude "Extrude6" cut of existing geometry blind -1
extrude "Extrude7" add of existing geometry blind 0.5
extrude "Extrude8" cut sketch "Sketch24" profile of L9 L10 L11 L12 along normal blind 2
extrude "Extrude9" cut sketch "Sketch20" profile of C2 L1 L2 L7 L8 L9 L10 L11 along normal blind 2
extrude "Extrude10" cut sketch "Sketch24" profile of L17 L18 L19 L20 along normal blind 2
extrude "Extrude11" cut sketch "Sketch24" profile of L13 L14 L15 L16 along normal blind 2
extrude "Extrude12" cut of existing geometry blind -2
extrude "Extrude13" add of existing geometry blind 1.5
extrude "Extrude14" cut sketch "Sketch24" profile of L17 L18 L19 L20 along normal blind 2
extrude "Extrude15" cut of existing geometry blind -1
extrude "Extrude16" add of existing geometry blind 1.5
extrude "Extrude17" cut sketch "Sketch24" profile of L13 L14 L15 L16 along normal blind 2
extrude "Extrude18" cut of existing geometry blind -2
extrude "Extrude19" new body sketch "Sketch24" profile of C14 against normal blind 5
extrude "Extrude20" new body sketch "Sketch24" profile of C13 against normal blind 5
extrude "Extrude21" new body sketch "Sketch24" profile of C8 against normal blind 5
extrude "Extrude22" new body sketch "Sketch24" profile of C11 against normal blind 5
extrude "Extrude23" new body sketch "Sketch24" profile of C19 against normal blind 5
extrude "Extrude24" new body sketch "Sketch24" profile of C20 against normal blind 5
pcb "PCB1" BoardHeight 1.57 named "d1_6"
revolve "Revolve1" sketch "Sketch22" AlongAngle 90
extrude "Extrude1" add of existing geometry to an object
combine "Combine1"
position "Position15"
sketch "Sketch25" plane through (0, -88, 0) normal (0, -1, 0) x axis (1, 0, 0)
  line L1 (-54.1235, 39.1897) -> (-50.7211, 39.2347)
  line L2 (-57.0548, 34.7842) -> (-57.0711, 32.8847)
  line L3 (-50.7211, 39.2347) -> (-57.0711, 32.8847)
  circle C1 centre (-29.1311, 34.1547) radius 1.796
  circle C2 centre (-29.1311, 34.1547) radius 1.796
  circle C3 centre (-29.1311, 34.1547) radius 1
  arc A1 centre (0, 0) radius 66.8221 clockwise from (-63.7853, 19.9155) to (-49.2565, 45.1551)
  circle C4 centre (0, 0) radius 66.8221
  dimension "d296" diameter C3 = 2
remove_instance "RemoveInstance5"
extrude "Extrude25" cut of existing geometry blind -1
extrude "Extrude26" cut of existing geometry blind -0.5
extrude "Extrude27" cut of existing geometry blind -0.5
extrude "Extrude28" cut of existing geometry blind -0.5
sketch "Sketch26" plane through (0, -88, 0) normal (0, 1, 0) x axis (-1, 0, 0)
  line L1 (-23.1918, -16.2634) -> (-23.5625, -16.634)
  line L2 (-16.2151, -23.1436) -> (-23.1918, -16.2634)
  line L3 (-14.1336, -23.6506) -> (-16.2151, -23.1436)
  line L4 (-12.7273, -22.2443) -> (-14.1336, -23.6506)
  line L5 (-8.9488, -26.0227) -> (-12.7273, -22.2443)
  line L6 (-16.2634, 23.1918) -> (-16.634, 23.5625)
  line L7 (-23.1436, 16.2151) -> (-16.2634, 23.1918)
  line L8 (-23.6506, 14.1336) -> (-23.1436, 16.2151)
  line L9 (-22.2443, 12.7273) -> (-23.6506, 14.1336)
  line L10 (-26.0227, 8.9488) -> (-22.2443, 12.7273)
  line L11 (23.1918, 16.2634) -> (23.5625, 16.634)
  line L12 (16.2151, 23.1436) -> (23.1918, 16.2634)
  line L13 (14.1336, 23.6506) -> (16.2151, 23.1436)
  line L14 (12.7273, 22.2443) -> (14.1336, 23.6506)
  line L15 (8.9488, 26.0227) -> (12.7273, 22.2443)
  line L16 (16.2634, -23.1918) -> (16.634, -23.5625)
  line L17 (23.1436, -16.2151) -> (16.2634, -23.1918)
  line L18 (23.6506, -14.1336) -> (23.1436, -16.2151)
  line L19 (22.2443, -12.7273) -> (23.6506, -14.1336)
  line L20 (26.0227, -8.9488) -> (22.2443, -12.7273)
  line L21 (-49.14, 45.2819) -> (-46.4886, 42.382)
  line L22 (-59.9456, 19.0649) -> (-63.7337, 20.0799)
  line L23 (-13.4596, -61.4513) -> (-59.9456, 19.0649)
  line L24 (-14.6453, -65.1974) -> (-13.4596, -61.4513)
  line L25 (13.4622, -61.4469) -> (14.4772, -65.235)
  line L26 (59.9482, 19.0693) -> (13.4622, -61.4469)
  line L27 (63.7853, 19.9155) -> (59.9482, 19.0693)
  line L28 (46.4835, 42.382) -> (49.2565, 45.1551)
  line L29 (-46.4886, 42.382) -> (46.4835, 42.382)
  arc A1 centre (-12.9929, -16.2499) radius 10.5766 clockwise from (-8.9488, -26.0227) to (-23.5625, -16.634)
  arc A2 centre (-16.2499, 12.9929) radius 10.5766 clockwise from (-26.0227, 8.9488) to (-16.634, 23.5625)
  arc A3 centre (12.9929, 16.2499) radius 10.5766 clockwise from (8.9488, 26.0227) to (23.5625, 16.634)
  arc A4 centre (16.2499, -12.9929) radius 10.5766 clockwise from (26.0227, -8.9488) to (16.634, -23.5625)
  arc A5 centre (0, 0) radius 66.8221 clockwise from (-63.7337, 20.0799) to (-49.14, 45.2819)
  arc A6 centre (0, 0) radius 66.8221 clockwise from (14.4772, -65.235) to (-14.6453, -65.1974)
  arc A7 centre (0, 0) radius 66.8221 clockwise from (49.2565, 45.1551) to (63.7853, 19.9155)
extrude "Extrude29" add sketch "Sketch26" along normal blind 3 taper -10
extrude "Extrude30" add sketch "Sketch26" along normal blind 3 taper -10
extrude "Extrude31" add sketch "Sketch26" along normal blind 3 taper -10
extrude "Extrude32" add sketch "Sketch26" along normal blind 3 taper -10
work_plane "WorkPlane9" AlongDistance 40
sketch "Sketch27" plane through (0, -88, 0) normal (0, -1, 0) x axis (1, 0, 0)
sketch "Sketch28" plane through (47.1843, -46, 47.1843) normal (0.7071, 0, 0.7071) x axis (0.7071, 0, -0.7071)
  circle C1 centre (0, -25) radius 7.5
  dimension "d315" diameter C1 = 15
sketch "Sketch29" plane through (0, 0, 0) normal (0, 1, 0) x axis (1, 0, 0)
  circle C1 centre (82, 0) radius 9
  dimension "d316" diameter C1 = 18
place_component sketch "Sketch29"
extrude "Extrude1" new body sketch "Sketch29" along normal blind 65
sketch "Sketch30" plane through (0, 0, 0) normal (0, 1, 0) x axis (1, 0, 0)
  line L1 (105, -50) -> (70, -50)
  line L2 (105, -108) -> (105, -50)
  line L3 (70, -108) -> (105, -108)
  line L4 (70, -50) -> (70, -108)
  point P2 (70, -50)
  point P3 (105, -50)
  point P4 (105, -108)
  dimension "d319" distance P2 P3 = 35
  dimension "d320" distance P3 P4 = 58
position "Position17"
sketch "Sketch31" plane through (34.5, 0, 0) normal (1, 0, 0) x axis (0, 0, -1)
  line L1 (-59, -88) -> (-45, -88)
  line L2 (-45.2819, -66) -> (-45.2819, -88)
  line L3 (-43.8767, -66.0153) -> (-45.2819, -66)
  line L4 (-45.2819, -66) -> (-43.8767, -66.0153)
  line L5 (-45.1551, -88) -> (-19.9155, -88)
  line L6 (-26.0227, -88) -> (-22.2443, -88)
  line L7 (-16.634, -88) -> (-26.8264, -88)
  line L8 (-25, -88) -> (-25, -66)
  line L9 (-26.1256, -66.0018) -> (-25, -66)
  circle C1 centre (-35, -67.5) radius 9
work_plane "WorkPlane10" sketch "Sketch31" AlongDistance -16
sketch "Sketch32" plane through (18.5, -77, 35.141) normal (1, 0, 0) x axis (0, 0, -1)
  line L1 (-10.141, 11) -> (-10.141, -11)
  line L2 (-10.141, 11) -> (-8.7357, 10.9847)
  line L3 (9.0154, 10.9982) -> (10.141, 11)
  line L4 (10.141, -11) -> (10.141, 11)
  line L5 (-10.141, -11) -> (15.0611, -11)
  circle C1 centre (0.141, 9.5) radius 9
  arc A1 centre (-13.3396, -9) radius 6.6476 clockwise from (-10.141, -3.1725) to (-7, -11)
extrude "Extrude33" add sketch "Sketch32" along normal blind 2
work_plane "WorkPlane11" AlongDistance 32
sketch "Sketch33" plane through (-13.5, -77, 35.141) normal (-1, 0, 0) x axis (0, 0, -1)
  line L1 (9.0154, -10.9982) -> (10.141, -11)
  line L2 (-10.141, -11) -> (-8.7357, -10.9847)
  line L3 (-10.141, 3.1725) -> (-10.141, -11)
  line L4 (10.141, 11) -> (-7, 11)
  line L5 (10.141, -11) -> (10.141, 11)
  arc A1 centre (0.141, -9.5) radius 9 clockwise from (-8.7357, -10.9847) to (9.0154, -10.9982)
  arc A2 centre (-13.3396, 9) radius 6.6476 clockwise from (-7, 11) to (-10.141, 3.1725)
extrude "Extrude34" add sketch "Sketch33" along normal blind 2.5
sketch "Sketch34" plane through (0, 2, 0) normal (0, 1, 0) x axis (-1, 0, 0)
  line L1 (-105, 108) -> (-70, 108)
  line L2 (-105, 50) -> (-105, 108)
  line L3 (-70, 50) -> (-105, 50)
  line L4 (-70, 108) -> (-70, 50)
  line L5 (-95, 50) -> (-85, 50)
  line L6 (-95, 60) -> (-95, 50)
  line L7 (-85, 60) -> (-95, 60)
  line L8 (-85, 50) -> (-85, 60)
  line L9 (-103.0398, 53) -> (-98, 53)
  line L10 (-103.0398, 60) -> (-103.0398, 53)
  line L11 (-98, 60) -> (-103.0398, 60)
  line L12 (-98, 53) -> (-98, 60)
  line L13 (-115, 79.875) -> (-98, 79.875)
  line L14 (-115, 100) -> (-115, 79.875)
  line L15 (-98, 100) -> (-115, 100)
  line L16 (-98, 79.875) -> (-98, 100)
  line L17 (-92.3671, 89.9375) -> (-81.9912, 89.9375)
  line L18 (-92.3671, 101.957) -> (-92.3671, 89.9375)
  line L19 (-81.9912, 101.957) -> (-92.3671, 101.957)
  line L20 (-81.9912, 89.9375) -> (-81.9912, 101.957)
sketch "Sketch35" plane through (87.5, 0, 79) normal (0, 1, 0) x axis (1, 0, 0)
  line L1 (17.5, 14) -> (-17.5, 14)
  line L2 (17.5, -21) -> (17.5, 14)
  line L3 (-17.5, -16) -> (17.5, -16)
  line L4 (-17.5, 14) -> (-17.5, -16)
  line L5 (-17.5, -29) -> (-17.5, 29)
  line L6 (-17.5, 29) -> (-17.5, -29)
  line L7 (17.5, 29) -> (-17.5, 29)
  line L8 (-17.5, -29) -> (17.5, -29)
  dimension "d341" distance L1 L7 = 15
  dimension "d342" distance L3 L8 = 13
sketch "Sketch36" plane through (0, 0, -10.1398) normal (0, 0, -1) x axis (-1, 0, 0)
  line L1 (54.685, -79.7761) -> (49.0282, -85.433)
  line L2 (29.9363, -55.0274) -> (54.685, -79.7761)
  line L3 (24.2795, -60.6842) -> (29.9363, -55.0274)
  line L4 (34.8861, -85.433) -> (24.2795, -74.8264)
  arc A1 centre (41.9571, -78.3619) radius 10 clockwise from (49.0282, -85.433) to (34.8861, -85.433)
  arc A2 centre (31.3505, -67.7553) radius 10 clockwise from (24.2795, -74.8264) to (24.2795, -60.6842)
  circle C1 centre (29, -67) radius 9
  circle C2 centre (41.9571, -79.4855) radius 9
  dimension "d346" diameter C1 = 18
  dimension "d347" diameter C2 = 18
pcb "PCB1" BoardHeight 1.57 named "d1_7"
pcb "PCB1" BoardHeight 1.57 named "d1_4"
sketch "Sketch37" plane through (0, 0, 0) normal (0, 0, -1) x axis (-1, 0, 0)
  line L1 (-39.116, 42.799) -> (-39.116, 46.609)
  line L2 (-37.465, 41.148) -> (-39.116, 42.799)
  line L3 (-1.905, 41.148) -> (-37.465, 41.148)
  line L4 (2.032, 45.085) -> (-1.905, 41.148)
  line L5 (2.159, 45.085) -> (2.032, 45.085)
  line L6 (2.159, 71.755) -> (2.159, 45.085)
  line L7 (-1.016, 74.93) -> (2.159, 71.755)
  line L8 (-13.081, 74.93) -> (-1.016, 74.93)
  line L9 (-14.351, 73.66) -> (-13.081, 74.93)
  line L10 (-29.591, 73.66) -> (-14.351, 73.66)
  line L11 (-30.734, 74.803) -> (-29.591, 73.66)
  line L12 (-40.767, 74.803) -> (-30.734, 74.803)
  line L13 (-41.148, 74.422) -> (-40.767, 74.803)
  line L14 (-51.435, 74.422) -> (-41.148, 74.422)
  line L15 (-54.61, 71.247) -> (-51.435, 74.422)
  line L16 (-54.61, 65.151) -> (-54.61, 71.247)
  line L17 (-55.753, 64.008) -> (-54.61, 65.151)
  line L18 (-55.753, 51.308) -> (-55.753, 64.008)
  line L19 (-52.07, 47.625) -> (-55.753, 51.308)
  line L20 (-40.386, 47.625) -> (-52.07, 47.625)
  line L21 (-40.259, 47.752) -> (-40.386, 47.625)
  line L22 (-39.116, 46.609) -> (-40.259, 47.752)
  line L23 (-17.3722, 57.9755) -> (-44.3722, 57.9755)
  line L24 (-44.6385, 74.4734) -> (-44.3722, 57.9755)
  line L25 (-44.1059, 41.4776) -> (-44.3722, 57.9755)
  circle C1 centre (-51.435, 51.41) radius 1.016
  circle C2 centre (-14.732, 65.938) radius 1.016
  circle C3 centre (-14.732, 55.982) radius 1.016
  circle C4 centre (-51.435, 61.366) radius 1.016
  circle C5 centre (-51.435, 61.366) radius 1.016
  circle C6 centre (-14.732, 65.938) radius 1.016
  circle C7 centre (-14.732, 55.982) radius 1.016
  point P28 (-44.3722, 57.9755)
  point P29 (-17.3722, 57.9755)
  point P30 (-44.6385, 74.4734)
  point P31 (-44.1059, 41.4776)
  dimension "d348" distance P28 P29 = 27
  dimension "d349" distance P28 P30 = 16.5
  dimension "d350" distance P28 P31 = 16.5
work_plane "WorkPlane12" RotateAngle 90
sketch "Sketch38" plane through (55.753, 57.658, 0) normal (-1, 0, 0) x axis (0, 0, -1)
  line L1 (0, 16.1804) -> (0, -0.3175)
  line L2 (0, -16.8154) -> (0, -0.3175)
  line L3 (8.2477, -8.7107) -> (0, -16.8154)
  line L4 (0, -0.3175) -> (8.2477, -8.7107)
  line L5 (8.2286, 8.5103) -> (0, -0.3175)
  line L6 (0, 16.1804) -> (8.2286, 8.5103)
  circle C1 centre (8.2477, -8.7107) radius 8.25
  circle C2 centre (8.2286, 8.5103) radius 8.25
  dimension "d352" diameter C1 = 16.5
  dimension "d353" angle L3 L4 = 90
  dimension "d354" diameter C2 = 16.5
  dimension "d355" angle L5 L6 = 90
extrude "Extrude1" new body sketch "Sketch38" profile of L2 C1 along normal blind 22
extrude "Extrude1" new body sketch "Sketch38" profile of L1 C2 along normal blind 22
extrude "Extrude2" add of existing geometry blind 5
extrude "Extrude2" add of existing geometry blind 5
move "Move1"
move "Move2"
move "Move2"
sketch "Sketch39" plane through (40.753, 0, 0) normal (1, 0, 0) x axis (0, 0, -1)
  line L1 (0.3358, 50.5253) -> (0.3358, 51.7133)
  line L2 (13.8626, 57.4432) -> (3.2298, 44.826)
  line L3 (11.7683, 54.958) -> (5.3242, 47.3112)
  arc A1 centre (8.5644, 51.1193) radius 8.25 clockwise from (0.3358, 51.7133) to (0.3358, 50.5253)
  circle C1 centre (5.8764, 47.9665) radius 0.75
  circle C2 centre (11.2574, 54.3519) radius 0.75
  point P7 (5.3242, 47.3112)
  point P8 (11.7683, 54.958)
  point P5 (3.2298, 44.826)
  point P6 (13.8626, 57.4432)
  dimension "d364" distance P7 P8 = 10
  dimension "d365" distance P5 P7 = 3.25
  dimension "d366" distance P6 P8 = 3.2499
  dimension "d367" diameter C1 = 1.5
  dimension "d368" diameter C2 = 1.5
loft "Loft1" sketch "Sketch39" + "Sketch37"
loft "Loft2" sketch "Sketch37" + "Sketch39"
sketch "Sketch40" plane through (16.753, 0, 0) normal (-1, 0, 0) x axis (0, 0, 1)
  line L1 (-3.3191, 61.2248) -> (-3.6408, 60.9995)
  line L2 (-0.4521, 65.0632) -> (-15.9309, 70.7767)
  line L3 (-6.0142, 75.8205) -> (-10.2846, 59.8832)
  line L4 (0, 74.4734) -> (0, 57.9755)
  arc A1 centre (-8.2106, 67.8682) radius 8.25 clockwise from (-3.6408, 60.9995) to (-3.3191, 61.2248)
  circle C1 centre (-9.2494, 63.7464) radius 0.75
  circle C2 centre (-7.0495, 71.9568) radius 0.75
  point P11 (-9.2494, 63.7464)
  point P12 (-7.0495, 71.9568)
  point P8 (-6.0142, 75.8205)
  dimension "d369" angle L3 L4 = 15
  dimension "d370" diameter C1 = 1.5
  dimension "d371" diameter C2 = 1.5
  dimension "d372" distance P11 P12 = 8.5
  dimension "d373" distance P8 P12 = 4
loft "Loft1" sketch "Sketch37" + "Sketch40"
loft "Loft2" sketch "Sketch37" + "Sketch40"
extrude "Extrude5" new body of existing geometry blind 3.5
extrude "Extrude6" add of existing geometry blind 16
copy_paste_bodies "CutPasteBodies1"
copy_paste_bodies "CutPasteBodies2"
extrude "Extrude3" new body of existing geometry blind 10
extrude "Extrude4" new body of existing geometry blind 10
extrude "Extrude5" new body of existing geometry blind 10
extrude "Extrude6" new body of existing geometry blind 4.5
extrude "Extrude7" new body of existing geometry blind 2.5
extrude "Extrude8" new body of existing geometry blind 3
combine "Combine1"
move "Move3"
move "Move4"
sketch "Sketch41" plane through (0, 0, -10.378) normal (0, 0, -1) x axis (-1, 0, 0)
  line L1 (48.7395, -71.0373) -> (49.6496, -71.801)
  line L2 (48.2906, -85.5807) -> (48.5431, -88)
  line L3 (48.4707, -84.5943) -> (48.2906, -85.5807)
  line L4 (29.584, -74.7547) -> (29.584, -88)
  line L5 (35.9459, -79.8929) -> (32.1731, -74.8895)
  line L6 (29.584, -88) -> (48.5431, -88)
  line L7 (46.4835, -88) -> (49.2565, -88)
  line L8 (59.9482, -88) -> (13.4622, -88)
  arc A1 centre (43.9053, -77.7226) radius 8.25 clockwise from (49.6496, -71.801) to (48.7395, -71.0373)
  arc A2 centre (31.3023, -66.6856) radius 8.25 clockwise from (39.5014, -67.6) to (39.5357, -67.2089)
  arc A3 centre (31.3023, -66.6856) radius 8.25 clockwise from (39.5014, -67.6) to (35.9631, -59.8784)
  arc A4 centre (43.9053, -77.7226) radius 8.25 clockwise from (48.4707, -84.5943) to (35.9459, -79.8929)
sketch "Sketch42" plane through (0, -42, 0) normal (0, 1, 0) x axis (-1, 0, 0)
  line L1 (16.85, -20.95) -> (-16.85, -20.95)
  line L2 (20.95, -16.85) -> (16.85, -20.95)
  line L3 (20.95, 16.85) -> (20.95, -16.85)
  line L4 (16.85, 20.95) -> (20.95, 16.85)
  line L5 (-16.85, 20.95) -> (16.85, 20.95)
  line L6 (-20.95, 16.85) -> (-16.85, 20.95)
  line L7 (-20.95, -16.85) -> (-20.95, 16.85)
  line L8 (-16.85, -20.95) -> (-20.95, -16.85)
  line L9 (-20.95, 16.85) -> (-16.85, 20.95)
  line L10 (-16.85, -20.95) -> (-20.95, -16.85)
  line L11 (16.85, -20.95) -> (-16.85, -20.95)
  line L12 (20.95, -16.85) -> (16.85, -20.95)
  line L13 (20.95, 16.85) -> (20.95, -16.85)
  line L14 (16.85, 20.95) -> (20.95, 16.85)
  line L15 (-16.85, 20.95) -> (16.85, 20.95)
  line L16 (-20.95, -16.85) -> (-20.95, 16.85)
  circle C1 centre (14.8, 14.8) radius 2.05
  circle C2 centre (-14.8, 14.8) radius 2.05
  circle C3 centre (14.8, -14.8) radius 2.05
  circle C4 centre (0, 0) radius 11
  circle C5 centre (-14.8, -14.8) radius 2.05
  circle C6 centre (0, 0) radius 15
extrude "Extrude1" new body of existing geometry blind 3
combine "Combine2"
extrude "Extrude35" add of existing geometry blind 3
extrude "Extrude36" add of existing geometry blind 3
extrude "Extrude37" add of existing geometry blind 3
extrude "Extrude38" add of existing geometry blind 3
extrude "Extrude39" add of existing geometry blind 3
extrude "Extrude40" add of existing geometry blind 3
combine "Combine3"
extrude "Extrude41" add sketch "Sketch41" profile of A1 L2 L3 A2 L4 A3 L5 A4 L6 against normal blind 20
sketch "Sketch43" plane through (0, -89.5, 0) normal (0, 1, 0) x axis (-1, 0, 0)
  line L1 (41.0955, -46.8205) -> (56.5955, -19.9737)
  line L2 (28.9711, -39.8205) -> (41.0955, -46.8205)
  line L3 (44.4711, -12.9737) -> (28.9711, -39.8205)
  line L4 (56.5955, -19.9737) -> (44.4711, -12.9737)
  line L5 (14.4772, -65.235) -> (13.4622, -61.4469)
  line L6 (59.9482, 19.0693) -> (63.7853, 19.9155)
  line L7 (13.4622, -61.4469) -> (59.9482, 19.0693)
  line L8 (49.2506, 0.5405) -> (42.4884, -11.1719)
  line L9 (49.6496, -10.378) -> (49.2506, 0.5405)
  line L10 (48.4707, -10.378) -> (35.9459, -10.378)
  line L11 (42.9468, -10.378) -> (49.6496, -10.378)
  circle C1 centre (53.7341, -1.5578) radius 1
  circle C2 centre (26.6831, -48.4115) radius 1
  arc A1 centre (0, 0) radius 66.8221 clockwise from (58.5079, -32.2803) to (14.4772, -65.235)
  arc A2 centre (58.7659, -30.5977) radius 1.7023 clockwise from (58.5079, -32.2803) to (59.9964, -29.4215)
  arc A3 centre (0, 0) radius 66.8221 clockwise from (63.7853, 19.9155) to (59.9964, -29.4215)
extrude "Extrude42" cut sketch "Sketch43" profile of L7 L8 L9 L10 L11 along normal blind 20
position "Position19"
